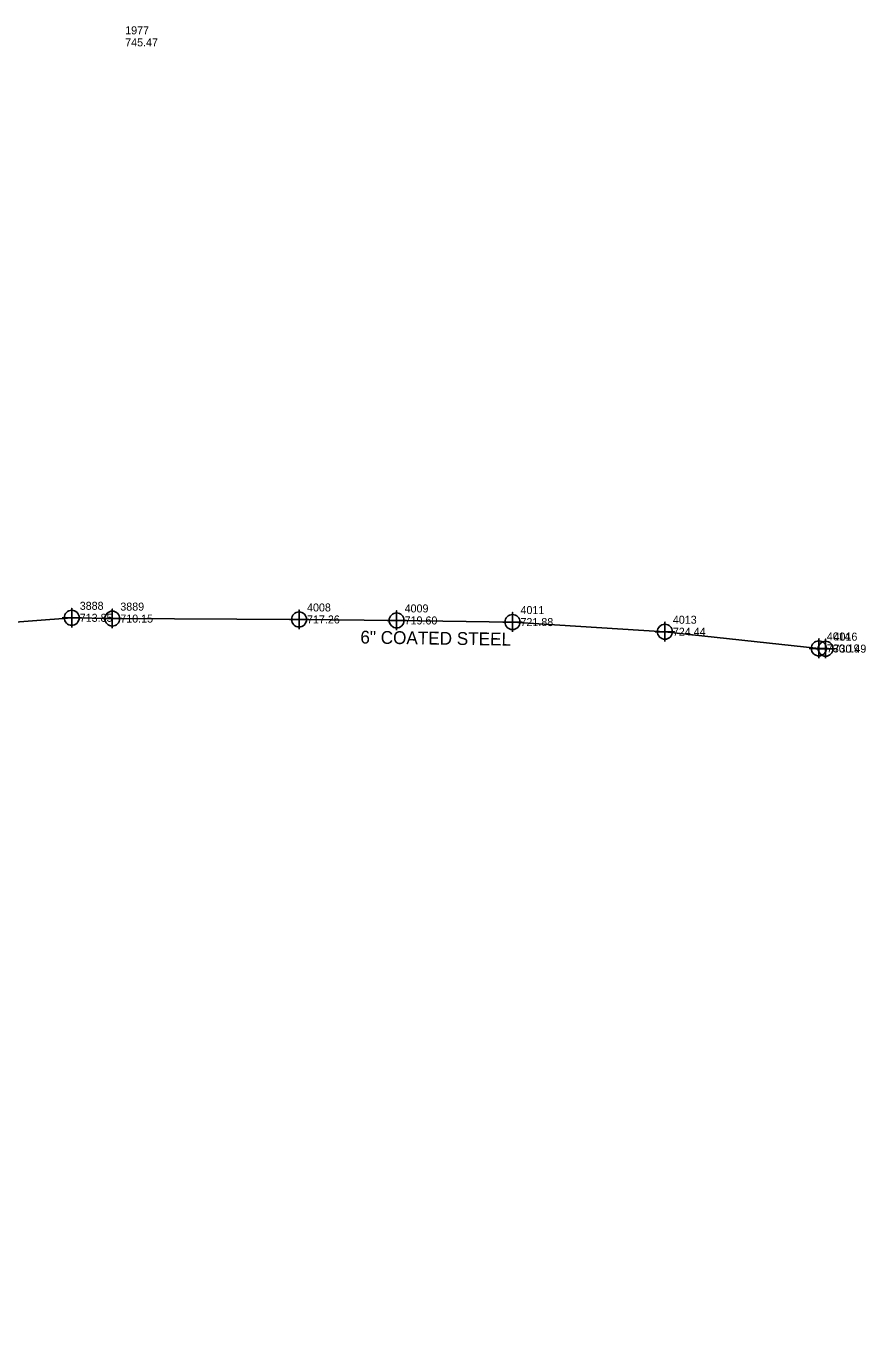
# Model space of a CAD drawing. Extents: x 1622486 to 1624761, y 758733 to 760816.
# Drawn here: x 1624195.1 to 1624457.5, y 759832 to 760241.5 of the extents above; entities that cross this region are included whole.
import ezdxf

# ---------------------------------------------------------------- set-up
doc = ezdxf.new("R2010")
doc.units = 0
for name, color, linetype in [('Exist Structure Minor Pipes RCP 30 Inch Text', 7, 'Continuous'), ('Exist Utilities Gas UG Line SUE', 7, 'Continuous'), ('Exist Utilities Gas UG Line SUE Cogo Elevation', 7, 'Continuous'), ('Exist Utilities Gas UG Line SUE Cogo Number', 7, 'Continuous'), ('Exist Utilities Gas UG Line SUE Cogo Point CELL', 7, 'Continuous'), ('Exist Utilities Other Traffic Signal Box Cogo Elevation', 7, 'Continuous'), ('Exist Utilities Other Traffic Signal Box Cogo Number', 7, 'Continuous')]:
    doc.layers.add(name, color=color, linetype=linetype)

msp = doc.modelspace()

# ---------------------------------------------------------------- linework, layer by layer
at = {"layer": 'Exist Utilities Gas UG Line SUE'}
msp.add_lwpolyline([(1623526, 759831.96), (1623567.48, 759856.55), (1623610.76, 759878.94), (1623655.07, 759898.59), (1623701.03, 759919.48), (1623744.33, 759939.8), (1623791, 759959.85), (1623836.2, 759978.89), (1623878.8, 759995.14), (1623920.16, 760009.52), (1623963.56, 760020.82), (1624009.71, 760029.98), (1624054.96, 760035.68), (1624106.85, 760041.87), (1624164.13, 760053.39), (1624209.29, 760056.8), (1624221.97, 760056.55), (1624280.33, 760056.28), (1624310.83, 760055.98), (1624347.04, 760055.47), (1624394.66, 760052.45), (1624442.78, 760047.24), (1624444.88, 760047.16)], dxfattribs=at)
at = {"layer": 'Exist Utilities Gas UG Line SUE Cogo Point CELL'}
for points in [[(1624206.29, 760056.8), (1624212.29, 760056.8), (1624209.29, 760056.8), (1624209.29, 760059.8), (1624209.29, 760053.8)], [(1624218.97, 760056.55), (1624224.97, 760056.55), (1624221.97, 760056.55), (1624221.97, 760059.55), (1624221.97, 760053.55)], [(1624277.33, 760056.28), (1624283.33, 760056.28), (1624280.33, 760056.28), (1624280.33, 760059.28), (1624280.33, 760053.28)], [(1624307.83, 760055.98), (1624313.83, 760055.98), (1624310.83, 760055.98), (1624310.83, 760058.98), (1624310.83, 760052.98)], [(1624344.04, 760055.47), (1624350.04, 760055.47), (1624347.04, 760055.47), (1624347.04, 760058.47), (1624347.04, 760052.47)], [(1624391.66, 760052.45), (1624397.66, 760052.45), (1624394.66, 760052.45), (1624394.66, 760055.45), (1624394.66, 760049.45)], [(1624439.78, 760047.24), (1624445.78, 760047.24), (1624442.78, 760047.24), (1624442.78, 760050.24), (1624442.78, 760044.24)], [(1624441.88, 760047.16), (1624447.88, 760047.16), (1624444.88, 760047.16), (1624444.88, 760050.16), (1624444.88, 760044.16)]]:
    msp.add_lwpolyline(points, dxfattribs=at)
for centre in [(1624209.29, 760056.8), (1624221.97, 760056.55), (1624280.33, 760056.28), (1624310.83, 760055.98), (1624347.04, 760055.47), (1624394.66, 760052.45), (1624442.78, 760047.24), (1624444.88, 760047.16)]:
    msp.add_circle(centre, 2.34, dxfattribs=at)

# ---------------------------------------------------------------- texts
at = {"layer": 'Exist Structure Minor Pipes RCP 30 Inch Text'}
msp.add_text('6" COATED STEEL', height=4, rotation=359.1789, dxfattribs=at).set_placement((1624299.47, 760048.78))
at = {"layer": 'Exist Utilities Gas UG Line SUE Cogo Elevation'}
for s, p in [('713.85', (1624211.79, 760055.55)), ('710.15', (1624224.47, 760055.3)), ('717.26', (1624282.83, 760055.03)), ('719.60', (1624313.33, 760054.73)), ('721.88', (1624349.54, 760054.22)), ('724.44', (1624397.16, 760051.2)), ('730.19', (1624445.28, 760045.99)), ('730.49', (1624447.38, 760045.91))]:
    msp.add_text(s, height=2.5, dxfattribs=at).set_placement(p)
at = {"layer": 'Exist Utilities Gas UG Line SUE Cogo Number'}
for s, p in [('3888', (1624211.79, 760059.3)), ('3889', (1624224.47, 760059.05)), ('4008', (1624282.83, 760058.78)), ('4009', (1624313.33, 760058.48)), ('4011', (1624349.54, 760057.97)), ('4013', (1624397.16, 760054.95)), ('4014', (1624445.28, 760049.74)), ('4016', (1624447.38, 760049.66))]:
    msp.add_text(s, height=2.5, dxfattribs=at).set_placement(p)
at = {"layer": 'Exist Utilities Other Traffic Signal Box Cogo Elevation'}
msp.add_text('745.47', height=2.5, dxfattribs=at).set_placement((1624226, 760235.26))
at = {"layer": 'Exist Utilities Other Traffic Signal Box Cogo Number'}
msp.add_text('1977', height=2.5, dxfattribs=at).set_placement((1624226, 760239.01))

doc.saveas('drawing.dxf')
